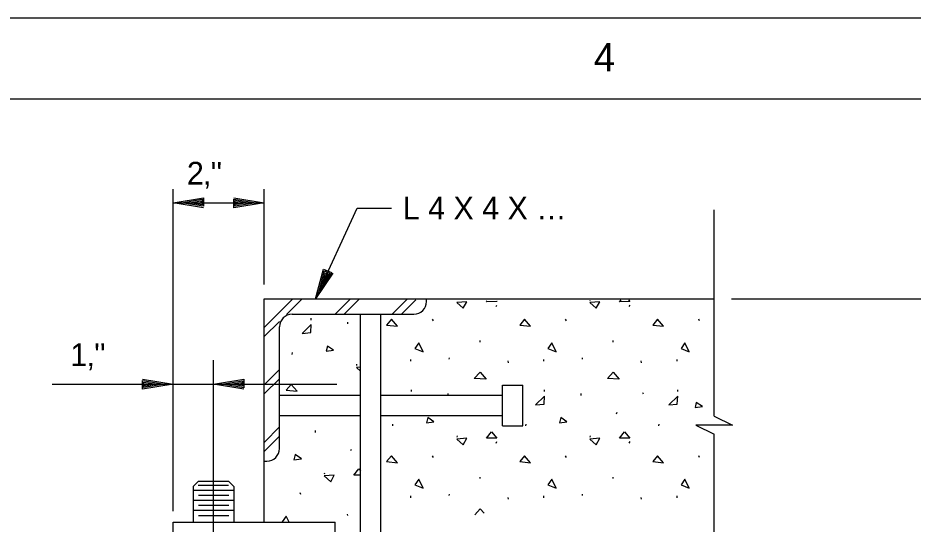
# Model space of a CAD drawing. Extents: x -0.2 to 13.5, y -0.2 to 9.5.
# Drawn here: x 3.071 to 4.91, y 8.293 to 9.333 of the extents above; entities that cross this region are included whole.
import ezdxf

# ---------------------------------------------------------------- set-up
doc = ezdxf.new("R2010")
doc.units = 0
for name, color, linetype in [('Level 1', 7, 'Continuous'), ('Level 10', 7, 'Continuous'), ('Level 13', 7, 'Continuous'), ('Level 2', 7, 'Continuous'), ('Level 3', 7, 'Continuous')]:
    doc.layers.add(name, color=color, linetype=linetype)

msp = doc.modelspace()

# ---------------------------------------------------------------- linework, layer by layer
at = {"layer": 'Level 1'}
for points in [[(0, 9.3333), (13.3333, 9.3333), (13.3333, 0), (0, 0)], [(0.5, 9.1667), (13.1667, 9.1667), (13.1667, 0.1667), (0.5, 0.1667)]]:
    msp.add_lwpolyline(points, close=True, dxfattribs=at)
at = {"layer": 'Level 10'}
for p, q in [((4.053, 8.7402), (4.0548, 8.7433)), ((4.3263, 8.7402), (4.3281, 8.7433)), ((3.6732, 8.7126), (3.6732, 8.7161)), ((3.7484, 8.7046), (3.7484, 8.7083)), ((3.9242, 8.711), (3.9225, 8.7143)), ((4.1975, 8.711), (4.1958, 8.7143)), ((4.4708, 8.711), (4.4691, 8.7143)), ((4.0205, 8.6674), (4.0202, 8.6705)), ((4.2938, 8.6674), (4.2935, 8.6705)), ((3.6344, 8.6419), (3.6349, 8.6455)), ((3.8781, 8.6279), (3.8781, 8.6316)), ((3.9569, 8.6323), (3.9574, 8.6351)), ((4.0786, 8.6249), (4.0776, 8.6286)), ((4.1514, 8.6279), (4.1514, 8.6316)), ((4.2302, 8.6323), (4.2307, 8.6351)), ((4.352, 8.6249), (4.3509, 8.6286)), ((4.4247, 8.6279), (4.4247, 8.6316)), ((3.7669, 8.6191), (3.7672, 8.6218)), ((3.8794, 8.5657), (3.8794, 8.5692)), ((4.1527, 8.5657), (4.1527, 8.5692)), ((4.426, 8.5657), (4.426, 8.5692)), ((4.2279, 8.5576), (4.2279, 8.5614)), ((4.3557, 8.5602), (4.3546, 8.5629)), ((4.3005, 8.5201), (4.3018, 8.5231)), ((3.8406, 8.495), (3.8411, 8.4986)), ((4.1139, 8.495), (4.1145, 8.4986)), ((4.3872, 8.495), (4.3878, 8.4986)), ((3.6823, 8.4817), (3.6823, 8.4854)), ((3.9731, 8.4721), (3.9734, 8.4749)), ((4.053, 8.4596), (4.0548, 8.4628)), ((4.2465, 8.4721), (4.2467, 8.4749)), ((4.3263, 8.4596), (4.3281, 8.4628)), ((3.7549, 8.4442), (3.7563, 8.4471)), ((3.9242, 8.4304), (3.9225, 8.4337)), ((4.1975, 8.4304), (4.1958, 8.4337)), ((4.4708, 8.4304), (4.4691, 8.4337)), ((3.7009, 8.3962), (3.7011, 8.3989)), ((4.0205, 8.3868), (4.0202, 8.3899)), ((4.2938, 8.3868), (4.2935, 8.3899)), ((3.6519, 8.3544), (3.6503, 8.3578)), ((3.8781, 8.3473), (3.8781, 8.3511)), ((3.9569, 8.3518), (3.9574, 8.3546)), ((4.0786, 8.3443), (4.0776, 8.3481)), ((4.1514, 8.3473), (4.1514, 8.3511)), ((4.2302, 8.3518), (4.2307, 8.3546)), ((4.352, 8.3443), (4.3509, 8.3481)), ((4.4247, 8.3473), (4.4247, 8.3511)), ((3.7482, 8.3109), (3.7479, 8.3139))]:
    msp.add_line(p, q, dxfattribs=at)
for points in [[(4.2465, 8.7527), (4.2465, 8.7535)], [(4.3066, 8.7501), (4.3097, 8.7541)], [(4.3248, 8.7542), (4.328, 8.7506)], [(4.0333, 8.7501), (4.0345, 8.7517)], [(4.0547, 8.7506), (4.0333, 8.7501)], [(4.0536, 8.7518), (4.0547, 8.7506)], [(4.328, 8.7506), (4.3066, 8.7501)], [(3.7748, 8.6156), (3.766, 8.615)], [(3.766, 8.615), (3.7748, 8.6072)], [(3.9546, 8.5579), (3.9546, 8.5614)], [(3.7611, 8.3936), (3.7711, 8.4069)], [(3.7711, 8.4069), (3.7748, 8.4027)], [(3.7748, 8.3939), (3.7611, 8.3936)], [(4.009, 8.3126), (4.0201, 8.3246)], [(4.0201, 8.3246), (4.0282, 8.3155)], [(3.622, 8.3094), (3.6139, 8.2976)], [(3.6139, 8.2976), (3.6144, 8.2974)], [(3.6279, 8.2974), (3.622, 8.3094)]]:
    msp.add_lwpolyline(points, dxfattribs=at)
for points in [[(3.9722, 8.7486), (3.9855, 8.7368), (3.9926, 8.7501)], [(4.2455, 8.7486), (4.2588, 8.7368), (4.266, 8.7501)], [(3.6722, 8.6866), (3.6732, 8.7033), (3.6547, 8.6852)], [(3.8505, 8.6997), (3.8381, 8.714), (3.8282, 8.7021)], [(4.1238, 8.6997), (4.1115, 8.714), (4.1015, 8.7021)], [(4.3971, 8.6997), (4.3848, 8.714), (4.3748, 8.7021)], [(3.8862, 8.6541), (3.9033, 8.6475), (3.8943, 8.666)], [(4.1595, 8.6541), (4.1766, 8.6475), (4.1676, 8.666)], [(4.4328, 8.6541), (4.4499, 8.6475), (4.4409, 8.666)], [(3.7039, 8.6485), (3.7191, 8.6504), (3.7064, 8.659)], [(4.0082, 8.5923), (4.0201, 8.6052), (4.0328, 8.591)], [(4.2815, 8.5923), (4.2934, 8.6052), (4.3061, 8.591)], [(3.6443, 8.5661), (3.6319, 8.5803), (3.622, 8.5685)], [(4.1518, 8.5396), (4.1527, 8.5563), (4.1342, 8.5383)], [(4.4251, 8.5396), (4.426, 8.5563), (4.4075, 8.5383)], [(4.4616, 8.5328), (4.4768, 8.5347), (4.464, 8.5433)], [(3.9101, 8.5015), (3.9253, 8.5035), (3.9126, 8.512)], [(4.1835, 8.5015), (4.1986, 8.5035), (4.1859, 8.512)], [(4.0333, 8.4695), (4.0434, 8.4828), (4.0547, 8.47)], [(4.3066, 8.4695), (4.3167, 8.4828), (4.328, 8.47)], [(3.9722, 8.4681), (3.9855, 8.4562), (3.9926, 8.4695)], [(4.2455, 8.4681), (4.2588, 8.4562), (4.266, 8.4695)], [(3.6379, 8.4256), (3.6531, 8.4275), (3.6403, 8.4361)], [(3.8505, 8.4191), (3.8381, 8.4334), (3.8282, 8.4216)], [(4.1238, 8.4191), (4.1115, 8.4334), (4.1015, 8.4216)], [(4.3971, 8.4191), (4.3848, 8.4334), (4.3748, 8.4216)], [(3.6999, 8.3921), (3.7133, 8.3803), (3.7204, 8.3936)], [(3.8862, 8.3736), (3.9033, 8.367), (3.8943, 8.3854)], [(4.1595, 8.3736), (4.1766, 8.367), (4.1676, 8.3854)], [(4.4328, 8.3736), (4.4499, 8.367), (4.4409, 8.3854)]]:
    msp.add_lwpolyline(points, close=True, dxfattribs=at)
at = {"layer": 'Level 13'}
msp.add_lwpolyline([(4.5009, 8.5152), (4.5384, 8.4966), (4.4634, 8.4966), (4.5009, 8.4779)], dxfattribs=at)
at = {"layer": 'Level 2'}
for p, q in [((4.5009, 8.5152), (4.5009, 8.9388)), ((3.5769, 8.7558), (4.5009, 8.7558)), ((3.5769, 8.2974), (3.5769, 8.7558)), ((3.9102, 8.7506), (3.9102, 8.7558)), ((3.9102, 8.7506), (3.9102, 8.7558)), ((3.6342, 8.7245), (3.8842, 8.7245)), ((3.7748, 8.2662), (3.7748, 8.7245)), ((3.8164, 8.2662), (3.8164, 8.7245)), ((3.6081, 8.4485), (3.6081, 8.6985)), ((4.0664, 8.4954), (4.0664, 8.5787)), ((4.0664, 8.5787), (4.1081, 8.5787)), ((4.1081, 8.4954), (4.1081, 8.5787)), ((3.6081, 8.5579), (3.7748, 8.5579)), ((3.8164, 8.5579), (4.0664, 8.5579)), ((3.6081, 8.5162), (3.7748, 8.5162)), ((3.8164, 8.5162), (4.0664, 8.5162)), ((4.0664, 8.4954), (4.1081, 8.4954)), ((4.5009, 7.1098), (4.5009, 8.4779)), ((3.5769, 8.4224), (3.5821, 8.4224)), ((3.4414, 8.3808), (3.431, 8.3704)), ((3.431, 8.3704), (3.431, 8.2974)), ((3.5033, 8.3726), (3.4411, 8.3726)), ((3.5039, 8.3808), (3.4414, 8.3808)), ((3.5144, 8.3704), (3.5039, 8.3808)), ((3.5144, 8.3704), (3.5144, 8.2974)), ((3.5144, 8.3626), (3.4307, 8.3626)), ((3.5038, 8.3522), (3.4416, 8.3522)), ((3.5144, 8.3417), (3.4307, 8.3417)), ((3.5038, 8.3313), (3.4416, 8.3313)), ((3.5144, 8.3209), (3.4307, 8.3209)), ((3.3894, 8.2974), (3.7227, 8.2974)), ((3.3894, 8.2349), (3.3894, 8.2974)), ((3.5038, 8.3104), (3.4416, 8.3104)), ((3.7227, 8.2349), (3.7227, 8.2974))]:
    msp.add_line(p, q, dxfattribs=at)
for points in [[(3.5769, 8.6973), (3.6351, 8.7555)], [(3.6223, 8.7238), (3.6539, 8.7554)], [(3.7215, 8.7241), (3.7524, 8.7549)], [(3.7404, 8.7241), (3.7712, 8.7548)], [(3.8397, 8.7244), (3.8697, 8.7544)], [(3.8586, 8.7245), (3.8884, 8.7543)], [(3.5769, 8.6784), (3.6082, 8.7097)], [(3.5769, 8.5795), (3.6081, 8.6107)], [(3.5769, 8.5606), (3.6081, 8.5918)], [(3.577, 8.4617), (3.6081, 8.4928)], [(3.577, 8.4428), (3.6081, 8.4739)]]:
    msp.add_lwpolyline(points, dxfattribs=at)
for centre, start, end in [((3.8842, 8.7506), 270, 0), ((3.6342, 8.6985), 90, 180), ((3.5821, 8.4485), 270, 0)]:
    msp.add_arc(centre, 0.026, start, end, dxfattribs=at)
at = {"layer": 'Level 3'}
for p, q in [((3.3894, 8.3197), (3.3894, 8.9815)), ((3.5769, 8.7856), (3.5769, 8.9815)), ((3.3894, 8.9536), (3.5769, 8.9536)), ((3.3894, 8.9536), (3.3894, 8.9536)), ((3.4067, 8.9536), (3.4067, 8.9536)), ((3.5595, 8.9536), (3.5595, 8.9536)), ((3.5769, 8.9536), (3.5769, 8.9536)), ((3.6821, 8.7563), (3.7676, 8.9427)), ((3.7676, 8.9427), (3.8379, 8.9427)), ((3.6894, 8.772), (3.6894, 8.772)), ((3.6821, 8.7563), (3.6821, 8.7563)), ((4.5364, 8.7558), (5.1492, 8.7558)), ((3.4727, 8.0555), (3.4727, 8.6304)), ((3.1414, 8.5807), (3.3894, 8.5807)), ((3.372, 8.5807), (3.372, 8.5807)), ((3.3894, 8.5807), (3.4727, 8.5807)), ((3.3894, 8.5807), (3.3894, 8.5807)), ((3.4727, 8.5807), (3.7259, 8.5807)), ((3.4727, 8.5807), (3.4727, 8.5807)), ((3.49, 8.5807), (3.49, 8.5807))]:
    msp.add_line(p, q, dxfattribs=at)
for points in [[(3.4517, 8.9432), (3.3894, 8.9536), (3.4517, 8.9639), (3.4517, 8.9462), (3.4067, 8.9536), (3.449, 8.9606), (3.449, 8.9492), (3.4234, 8.9536), (3.4464, 8.9572), (3.4464, 8.9526), (3.4407, 8.9536)], [(3.5145, 8.9639), (3.5769, 8.9536), (3.5145, 8.9432), (3.5145, 8.9609), (3.5595, 8.9536), (3.5172, 8.9466), (3.5172, 8.9579), (3.5429, 8.9536), (3.5199, 8.9499), (3.5199, 8.9546), (3.5255, 8.9536)], [(3.7175, 8.8086), (3.6821, 8.7563), (3.6987, 8.8172), (3.7148, 8.8099), (3.6894, 8.772), (3.7006, 8.8134), (3.7109, 8.8087), (3.6963, 8.7872), (3.7026, 8.8096), (3.7068, 8.8076), (3.7035, 8.8029)], [(3.327, 8.591), (3.3894, 8.5807), (3.327, 8.5704), (3.327, 8.588), (3.372, 8.5807), (3.3297, 8.5737), (3.3297, 8.585), (3.3554, 8.5807), (3.3324, 8.577), (3.3324, 8.5817), (3.338, 8.5807)], [(3.535, 8.5704), (3.4727, 8.5807), (3.535, 8.591), (3.535, 8.5734), (3.49, 8.5807), (3.5324, 8.5877), (3.5324, 8.5764), (3.5067, 8.5807), (3.5297, 8.5844), (3.5297, 8.5797), (3.524, 8.5807)]]:
    msp.add_lwpolyline(points, dxfattribs=at)

# ---------------------------------------------------------------- texts
at = {"layer": 'Level 1'}
msp.add_text('4', height=0.0584, dxfattribs=at).set_placement((4.2539, 9.2232))
at = {"layer": 'Level 3'}
for s, height, p in [("2‚''", 0.04667, (3.418, 8.9909)), ('L 4 X 4 X …', 0.046667, (3.8614, 8.9192)), ("1‚''", 0.04667, (3.1787, 8.618))]:
    msp.add_text(s, height=height, dxfattribs=at).set_placement(p)

doc.saveas('drawing.dxf')
